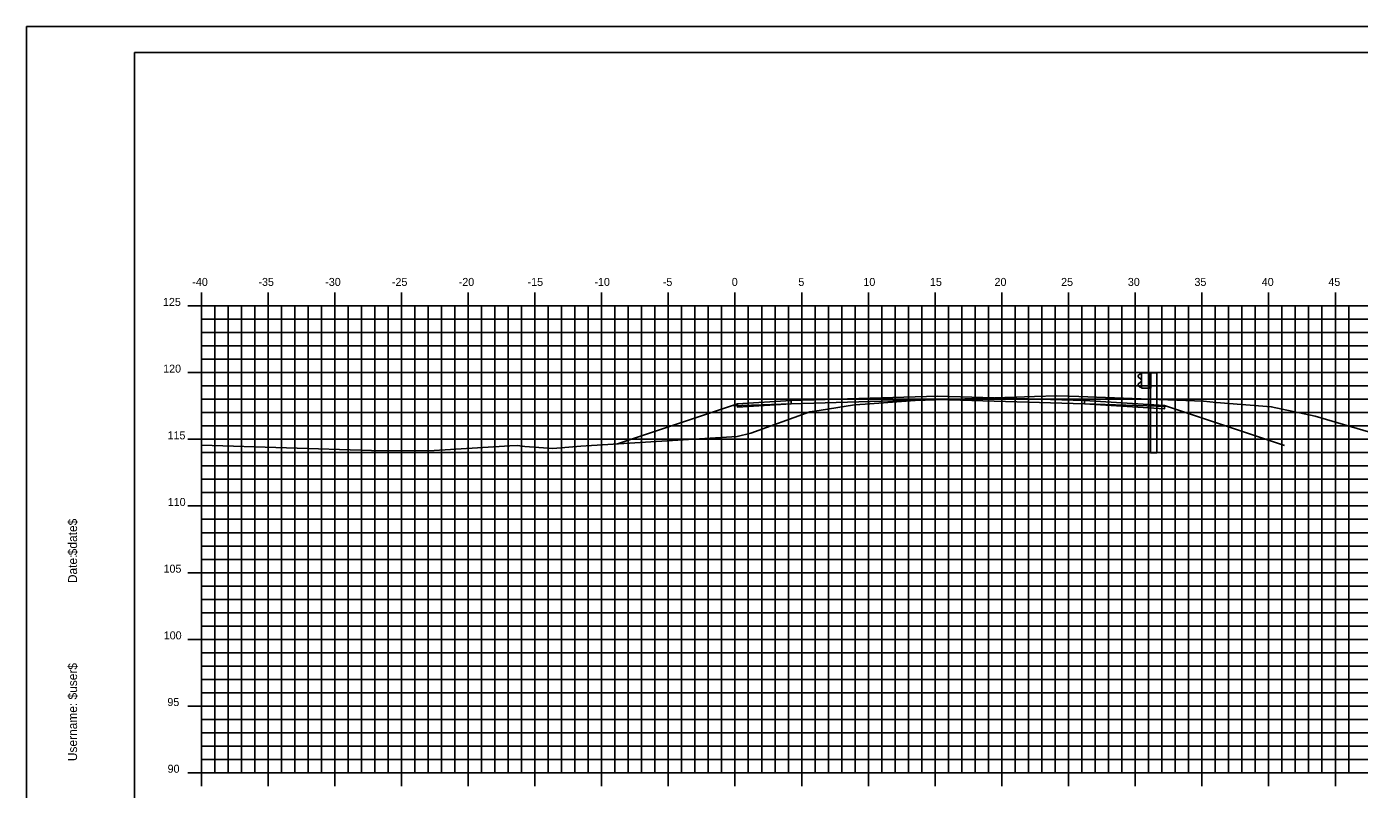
# Model space of a CAD drawing. Extents: x 850598 to 870284, y 366541 to 366651.
# Drawn here: x 851263.1 to 851363, y 366594 to 366651.2 of the extents above; entities that cross this region are included whole.
import ezdxf

# ---------------------------------------------------------------- set-up
doc = ezdxf.new("R2010")
doc.units = 0
for name, color, linetype in [('BORDER', 7, 'Continuous'), ('D_Guardrail_Beam_Rt', 7, 'Continuous'), ('D_Roadway_SubGrade', 7, 'Continuous'), ('H_V ANNOTATION', 7, 'Continuous'), ('MAJOR', 7, 'Continuous'), ('MINOR', 7, 'Continuous'), ('PLOT BOUNDARY', 7, 'Continuous'), ('S_Roadway_Centerline', 7, 'Continuous'), ('TEMPLATE', 7, 'Continuous')]:
    doc.layers.add(name, color=color, linetype=linetype)

msp = doc.modelspace()

# ---------------------------------------------------------------- linework, layer by layer
at = {"layer": 'BORDER'}
for p, q in [((851431.167, 366649.225), (851271.167, 366649.225)), ((851271.167, 366649.225), (851271.167, 366544.225))]:
    msp.add_line(p, q, dxfattribs=at)
at = {"layer": 'D_Guardrail_Beam_Rt'}
for p, q in [((851346.547, 366625.123), (851346.404, 366625.023)), ((851346.404, 366624.88), (851346.599, 366624.744)), ((851346.637, 366625.143), (851346.564, 366625.13)), ((851346.637, 366625.217), (851347.325, 366625.217)), ((851346.637, 366624.05), (851346.637, 366625.217)), ((851347.158, 366625.217), (851347.158, 366624.05)), ((851347.262, 366625.217), (851347.262, 366624.05)), ((851347.325, 366625.217), (851347.796, 366625.217)), ((851347.325, 366625.217), (851347.325, 366624.05)), ((851347.796, 366625.217), (851347.796, 366619.217)), ((851346.599, 366624.524), (851346.404, 366624.388)), ((851346.404, 366624.244), (851346.547, 366624.145)), ((851346.564, 366624.138), (851346.637, 366624.125)), ((851346.633, 366624.679), (851346.633, 366624.588)), ((851347.325, 366624.05), (851346.637, 366624.05)), ((851347.304, 366619.217), (851347.304, 366624.05)), ((851347.304, 366619.217), (851347.796, 366619.217))]:
    msp.add_line(p, q, dxfattribs=at)
for centre, major_axis, start_param, end_param in [((851346.454, 366624.951), (-0.0877, 0), 5.323254, 7.243116), ((851346.571, 366625.089), (-0.0417, 0), 4.886922, 5.323254), ((851346.454, 366624.316), (-0.0877, 0), 5.323254, 7.243116), ((851346.571, 366624.178), (-0.0417, 0), 0.959931, 1.396263), ((851346.554, 366624.679), (0.0789, 0), 0, 0.959931), ((851346.554, 366624.588), (0.0789, 0), 5.323254, 6.283185)]:
    msp.add_ellipse(centre, major_axis=major_axis, ratio=0.995501, start_param=start_param, end_param=end_param, dxfattribs=at)
at = {"layer": 'D_Roadway_SubGrade'}
msp.add_lwpolyline([(851357.367, 366619.764), (851348.367, 366622.764), (851342.367, 366623.124), (851331.367, 366623.454), (851320.367, 366623.124), (851316.367, 366622.884), (851307.367, 366619.884)], dxfattribs=at)
at = {"layer": 'MAJOR'}
for p, q in [((851276.167, 366631.227), (851276.167, 366630.225)), ((851276.167, 366631.227), (851276.167, 366630.225)), ((851281.167, 366631.227), (851281.167, 366630.225)), ((851281.167, 366631.227), (851281.167, 366630.225)), ((851286.167, 366631.227), (851286.167, 366630.225)), ((851286.167, 366631.227), (851286.167, 366630.225)), ((851291.167, 366631.227), (851291.167, 366630.225)), ((851291.167, 366631.227), (851291.167, 366630.225)), ((851296.167, 366631.227), (851296.167, 366630.225)), ((851296.167, 366631.227), (851296.167, 366630.225)), ((851301.167, 366631.227), (851301.167, 366630.225)), ((851301.167, 366631.227), (851301.167, 366630.225)), ((851306.167, 366631.227), (851306.167, 366630.225)), ((851306.167, 366631.227), (851306.167, 366630.225)), ((851311.167, 366631.227), (851311.167, 366630.225)), ((851311.167, 366631.227), (851311.167, 366630.225)), ((851316.167, 366631.227), (851316.167, 366630.225)), ((851316.167, 366631.227), (851316.167, 366630.225)), ((851321.167, 366631.227), (851321.167, 366630.225)), ((851321.167, 366631.227), (851321.167, 366630.225)), ((851326.167, 366631.227), (851326.167, 366630.225)), ((851326.167, 366631.227), (851326.167, 366630.225)), ((851331.167, 366631.227), (851331.167, 366630.225)), ((851331.167, 366631.227), (851331.167, 366630.225)), ((851336.167, 366631.227), (851336.167, 366630.225)), ((851336.167, 366631.227), (851336.167, 366630.225)), ((851341.167, 366631.227), (851341.167, 366630.225)), ((851341.167, 366631.227), (851341.167, 366630.225)), ((851346.167, 366631.227), (851346.167, 366630.225)), ((851346.167, 366631.227), (851346.167, 366630.225)), ((851351.167, 366631.227), (851351.167, 366630.225)), ((851351.167, 366631.227), (851351.167, 366630.225)), ((851356.167, 366631.227), (851356.167, 366630.225)), ((851356.167, 366631.227), (851356.167, 366630.225)), ((851361.167, 366631.227), (851361.167, 366630.225)), ((851361.167, 366631.227), (851361.167, 366630.225)), ((851275.165, 366630.225), (851276.167, 366630.225)), ((851275.165, 366630.225), (851276.167, 366630.225)), ((851276.167, 366630.225), (851416.167, 366630.225)), ((851276.167, 366595.225), (851276.167, 366630.225)), ((851276.167, 366595.225), (851276.167, 366630.225)), ((851276.167, 366630.225), (851416.167, 366630.225)), ((851276.167, 366630.225), (851416.167, 366630.225)), ((851276.167, 366595.225), (851276.167, 366630.225)), ((851276.167, 366595.225), (851276.167, 366630.225)), ((851276.167, 366630.225), (851416.167, 366630.225)), ((851281.167, 366595.225), (851281.167, 366630.225)), ((851281.167, 366595.225), (851281.167, 366630.225)), ((851286.167, 366595.225), (851286.167, 366630.225)), ((851286.167, 366595.225), (851286.167, 366630.225)), ((851291.167, 366595.225), (851291.167, 366630.225)), ((851291.167, 366595.225), (851291.167, 366630.225)), ((851296.167, 366595.225), (851296.167, 366630.225)), ((851296.167, 366595.225), (851296.167, 366630.225)), ((851301.167, 366595.225), (851301.167, 366630.225)), ((851301.167, 366595.225), (851301.167, 366630.225)), ((851306.167, 366595.225), (851306.167, 366630.225)), ((851306.167, 366595.225), (851306.167, 366630.225)), ((851311.167, 366595.225), (851311.167, 366630.225)), ((851311.167, 366595.225), (851311.167, 366630.225)), ((851316.167, 366595.225), (851316.167, 366630.225)), ((851316.167, 366595.225), (851316.167, 366630.225)), ((851321.167, 366595.225), (851321.167, 366630.225)), ((851321.167, 366595.225), (851321.167, 366630.225)), ((851326.167, 366595.225), (851326.167, 366630.225)), ((851326.167, 366595.225), (851326.167, 366630.225)), ((851331.167, 366595.225), (851331.167, 366630.225)), ((851331.167, 366595.225), (851331.167, 366630.225)), ((851336.167, 366595.225), (851336.167, 366630.225)), ((851336.167, 366595.225), (851336.167, 366630.225)), ((851341.167, 366595.225), (851341.167, 366630.225)), ((851341.167, 366595.225), (851341.167, 366630.225)), ((851346.167, 366595.225), (851346.167, 366630.225)), ((851346.167, 366595.225), (851346.167, 366630.225)), ((851351.167, 366595.225), (851351.167, 366630.225)), ((851351.167, 366595.225), (851351.167, 366630.225)), ((851356.167, 366595.225), (851356.167, 366630.225)), ((851356.167, 366595.225), (851356.167, 366630.225)), ((851361.167, 366595.225), (851361.167, 366630.225)), ((851361.167, 366595.225), (851361.167, 366630.225)), ((851275.165, 366625.225), (851276.167, 366625.225)), ((851275.165, 366625.225), (851276.167, 366625.225)), ((851276.167, 366625.225), (851416.167, 366625.225)), ((851276.167, 366625.225), (851416.167, 366625.225)), ((851275.165, 366620.225), (851276.167, 366620.225)), ((851275.165, 366620.225), (851276.167, 366620.225)), ((851276.167, 366620.225), (851416.167, 366620.225)), ((851276.167, 366620.225), (851416.167, 366620.225)), ((851275.165, 366615.225), (851276.167, 366615.225)), ((851275.165, 366615.225), (851276.167, 366615.225)), ((851276.167, 366615.225), (851416.167, 366615.225)), ((851276.167, 366615.225), (851416.167, 366615.225)), ((851275.165, 366610.225), (851276.167, 366610.225)), ((851275.165, 366610.225), (851276.167, 366610.225)), ((851276.167, 366610.225), (851416.167, 366610.225)), ((851276.167, 366610.225), (851416.167, 366610.225)), ((851275.165, 366605.225), (851276.167, 366605.225)), ((851275.165, 366605.225), (851276.167, 366605.225)), ((851276.167, 366605.225), (851416.167, 366605.225)), ((851276.167, 366605.225), (851416.167, 366605.225)), ((851275.165, 366600.225), (851276.167, 366600.225)), ((851275.165, 366600.225), (851276.167, 366600.225)), ((851276.167, 366600.225), (851416.167, 366600.225)), ((851276.167, 366600.225), (851416.167, 366600.225)), ((851275.165, 366595.225), (851276.167, 366595.225)), ((851275.165, 366595.225), (851276.167, 366595.225)), ((851276.167, 366595.225), (851416.167, 366595.225)), ((851276.167, 366595.225), (851416.167, 366595.225)), ((851276.167, 366594.223), (851276.167, 366595.225)), ((851276.167, 366595.225), (851416.167, 366595.225)), ((851276.167, 366595.225), (851416.167, 366595.225)), ((851276.167, 366594.223), (851276.167, 366595.225)), ((851281.167, 366594.223), (851281.167, 366595.225)), ((851281.167, 366594.223), (851281.167, 366595.225)), ((851286.167, 366594.223), (851286.167, 366595.225)), ((851286.167, 366594.223), (851286.167, 366595.225)), ((851291.167, 366594.223), (851291.167, 366595.225)), ((851291.167, 366594.223), (851291.167, 366595.225)), ((851296.167, 366594.223), (851296.167, 366595.225)), ((851296.167, 366594.223), (851296.167, 366595.225)), ((851301.167, 366594.223), (851301.167, 366595.225)), ((851301.167, 366594.223), (851301.167, 366595.225)), ((851306.167, 366594.223), (851306.167, 366595.225)), ((851306.167, 366594.223), (851306.167, 366595.225)), ((851311.167, 366594.223), (851311.167, 366595.225)), ((851311.167, 366594.223), (851311.167, 366595.225)), ((851316.167, 366594.223), (851316.167, 366595.225)), ((851316.167, 366594.223), (851316.167, 366595.225)), ((851321.167, 366594.223), (851321.167, 366595.225)), ((851321.167, 366594.223), (851321.167, 366595.225)), ((851326.167, 366594.223), (851326.167, 366595.225)), ((851326.167, 366594.223), (851326.167, 366595.225)), ((851331.167, 366594.223), (851331.167, 366595.225)), ((851331.167, 366594.223), (851331.167, 366595.225)), ((851336.167, 366594.223), (851336.167, 366595.225)), ((851336.167, 366594.223), (851336.167, 366595.225)), ((851341.167, 366594.223), (851341.167, 366595.225)), ((851341.167, 366594.223), (851341.167, 366595.225)), ((851346.167, 366594.223), (851346.167, 366595.225)), ((851346.167, 366594.223), (851346.167, 366595.225)), ((851351.167, 366594.223), (851351.167, 366595.225)), ((851351.167, 366594.223), (851351.167, 366595.225)), ((851356.167, 366594.223), (851356.167, 366595.225)), ((851356.167, 366594.223), (851356.167, 366595.225)), ((851361.167, 366594.223), (851361.167, 366595.225)), ((851361.167, 366594.223), (851361.167, 366595.225))]:
    msp.add_line(p, q, dxfattribs=at)
at = {"layer": 'MINOR'}
for p, q in [((851277.167, 366595.225), (851277.167, 366630.225)), ((851277.167, 366595.225), (851277.167, 366630.225)), ((851278.167, 366595.225), (851278.167, 366630.225)), ((851278.167, 366595.225), (851278.167, 366630.225)), ((851279.167, 366595.225), (851279.167, 366630.225)), ((851279.167, 366595.225), (851279.167, 366630.225)), ((851280.167, 366595.225), (851280.167, 366630.225)), ((851280.167, 366595.225), (851280.167, 366630.225)), ((851282.167, 366595.225), (851282.167, 366630.225)), ((851282.167, 366595.225), (851282.167, 366630.225)), ((851283.167, 366595.225), (851283.167, 366630.225)), ((851283.167, 366595.225), (851283.167, 366630.225)), ((851284.167, 366595.225), (851284.167, 366630.225)), ((851284.167, 366595.225), (851284.167, 366630.225)), ((851285.167, 366595.225), (851285.167, 366630.225)), ((851285.167, 366595.225), (851285.167, 366630.225)), ((851287.167, 366595.225), (851287.167, 366630.225)), ((851287.167, 366595.225), (851287.167, 366630.225)), ((851288.167, 366595.225), (851288.167, 366630.225)), ((851288.167, 366595.225), (851288.167, 366630.225)), ((851289.167, 366595.225), (851289.167, 366630.225)), ((851289.167, 366595.225), (851289.167, 366630.225)), ((851290.167, 366595.225), (851290.167, 366630.225)), ((851290.167, 366595.225), (851290.167, 366630.225)), ((851292.167, 366595.225), (851292.167, 366630.225)), ((851292.167, 366595.225), (851292.167, 366630.225)), ((851293.167, 366595.225), (851293.167, 366630.225)), ((851293.167, 366595.225), (851293.167, 366630.225)), ((851294.167, 366595.225), (851294.167, 366630.225)), ((851294.167, 366595.225), (851294.167, 366630.225)), ((851295.167, 366595.225), (851295.167, 366630.225)), ((851295.167, 366595.225), (851295.167, 366630.225)), ((851297.167, 366595.225), (851297.167, 366630.225)), ((851297.167, 366595.225), (851297.167, 366630.225)), ((851298.167, 366595.225), (851298.167, 366630.225)), ((851298.167, 366595.225), (851298.167, 366630.225)), ((851299.167, 366595.225), (851299.167, 366630.225)), ((851299.167, 366595.225), (851299.167, 366630.225)), ((851300.167, 366595.225), (851300.167, 366630.225)), ((851300.167, 366595.225), (851300.167, 366630.225)), ((851302.167, 366595.225), (851302.167, 366630.225)), ((851302.167, 366595.225), (851302.167, 366630.225)), ((851303.167, 366595.225), (851303.167, 366630.225)), ((851303.167, 366595.225), (851303.167, 366630.225)), ((851304.167, 366595.225), (851304.167, 366630.225)), ((851304.167, 366595.225), (851304.167, 366630.225)), ((851305.167, 366595.225), (851305.167, 366630.225)), ((851305.167, 366595.225), (851305.167, 366630.225)), ((851307.167, 366595.225), (851307.167, 366630.225)), ((851307.167, 366595.225), (851307.167, 366630.225)), ((851308.167, 366595.225), (851308.167, 366630.225)), ((851308.167, 366595.225), (851308.167, 366630.225)), ((851309.167, 366595.225), (851309.167, 366630.225)), ((851309.167, 366595.225), (851309.167, 366630.225)), ((851310.167, 366595.225), (851310.167, 366630.225)), ((851310.167, 366595.225), (851310.167, 366630.225)), ((851312.167, 366595.225), (851312.167, 366630.225)), ((851312.167, 366595.225), (851312.167, 366630.225)), ((851313.167, 366595.225), (851313.167, 366630.225)), ((851313.167, 366595.225), (851313.167, 366630.225)), ((851314.167, 366595.225), (851314.167, 366630.225)), ((851314.167, 366595.225), (851314.167, 366630.225)), ((851315.167, 366595.225), (851315.167, 366630.225)), ((851315.167, 366595.225), (851315.167, 366630.225)), ((851317.167, 366595.225), (851317.167, 366630.225)), ((851317.167, 366595.225), (851317.167, 366630.225)), ((851318.167, 366595.225), (851318.167, 366630.225)), ((851318.167, 366595.225), (851318.167, 366630.225)), ((851319.167, 366595.225), (851319.167, 366630.225)), ((851319.167, 366595.225), (851319.167, 366630.225)), ((851320.167, 366595.225), (851320.167, 366630.225)), ((851320.167, 366595.225), (851320.167, 366630.225)), ((851322.167, 366595.225), (851322.167, 366630.225)), ((851322.167, 366595.225), (851322.167, 366630.225)), ((851323.167, 366595.225), (851323.167, 366630.225)), ((851323.167, 366595.225), (851323.167, 366630.225)), ((851324.167, 366595.225), (851324.167, 366630.225)), ((851324.167, 366595.225), (851324.167, 366630.225)), ((851325.167, 366595.225), (851325.167, 366630.225)), ((851325.167, 366595.225), (851325.167, 366630.225)), ((851327.167, 366595.225), (851327.167, 366630.225)), ((851327.167, 366595.225), (851327.167, 366630.225)), ((851328.167, 366595.225), (851328.167, 366630.225)), ((851328.167, 366595.225), (851328.167, 366630.225)), ((851329.167, 366595.225), (851329.167, 366630.225)), ((851329.167, 366595.225), (851329.167, 366630.225)), ((851330.167, 366595.225), (851330.167, 366630.225)), ((851330.167, 366595.225), (851330.167, 366630.225)), ((851332.167, 366595.225), (851332.167, 366630.225)), ((851332.167, 366595.225), (851332.167, 366630.225)), ((851333.167, 366595.225), (851333.167, 366630.225)), ((851333.167, 366595.225), (851333.167, 366630.225)), ((851334.167, 366595.225), (851334.167, 366630.225)), ((851334.167, 366595.225), (851334.167, 366630.225)), ((851335.167, 366595.225), (851335.167, 366630.225)), ((851335.167, 366595.225), (851335.167, 366630.225)), ((851337.167, 366595.225), (851337.167, 366630.225)), ((851337.167, 366595.225), (851337.167, 366630.225)), ((851338.167, 366595.225), (851338.167, 366630.225)), ((851338.167, 366595.225), (851338.167, 366630.225)), ((851339.167, 366595.225), (851339.167, 366630.225)), ((851339.167, 366595.225), (851339.167, 366630.225)), ((851340.167, 366595.225), (851340.167, 366630.225)), ((851340.167, 366595.225), (851340.167, 366630.225)), ((851342.167, 366595.225), (851342.167, 366630.225)), ((851342.167, 366595.225), (851342.167, 366630.225)), ((851343.167, 366595.225), (851343.167, 366630.225)), ((851343.167, 366595.225), (851343.167, 366630.225)), ((851344.167, 366595.225), (851344.167, 366630.225)), ((851344.167, 366595.225), (851344.167, 366630.225)), ((851345.167, 366595.225), (851345.167, 366630.225)), ((851345.167, 366595.225), (851345.167, 366630.225)), ((851347.167, 366595.225), (851347.167, 366630.225)), ((851347.167, 366595.225), (851347.167, 366630.225)), ((851348.167, 366595.225), (851348.167, 366630.225)), ((851348.167, 366595.225), (851348.167, 366630.225)), ((851349.167, 366595.225), (851349.167, 366630.225)), ((851349.167, 366595.225), (851349.167, 366630.225)), ((851350.167, 366595.225), (851350.167, 366630.225)), ((851350.167, 366595.225), (851350.167, 366630.225)), ((851352.167, 366595.225), (851352.167, 366630.225)), ((851352.167, 366595.225), (851352.167, 366630.225)), ((851353.167, 366595.225), (851353.167, 366630.225)), ((851353.167, 366595.225), (851353.167, 366630.225)), ((851354.167, 366595.225), (851354.167, 366630.225)), ((851354.167, 366595.225), (851354.167, 366630.225)), ((851355.167, 366595.225), (851355.167, 366630.225)), ((851355.167, 366595.225), (851355.167, 366630.225)), ((851357.167, 366595.225), (851357.167, 366630.225)), ((851357.167, 366595.225), (851357.167, 366630.225)), ((851358.167, 366595.225), (851358.167, 366630.225)), ((851358.167, 366595.225), (851358.167, 366630.225)), ((851359.167, 366595.225), (851359.167, 366630.225)), ((851359.167, 366595.225), (851359.167, 366630.225)), ((851360.167, 366595.225), (851360.167, 366630.225)), ((851360.167, 366595.225), (851360.167, 366630.225)), ((851362.167, 366595.225), (851362.167, 366630.225)), ((851362.167, 366595.225), (851362.167, 366630.225)), ((851276.167, 366629.225), (851416.167, 366629.225)), ((851276.167, 366629.225), (851277.169, 366629.225)), ((851276.167, 366629.225), (851416.167, 366629.225)), ((851276.167, 366629.225), (851277.169, 366629.225)), ((851276.167, 366628.225), (851416.167, 366628.225)), ((851276.167, 366628.225), (851277.169, 366628.225)), ((851276.167, 366628.225), (851416.167, 366628.225)), ((851276.167, 366628.225), (851277.169, 366628.225)), ((851276.167, 366627.225), (851416.167, 366627.225)), ((851276.167, 366627.225), (851277.169, 366627.225)), ((851276.167, 366627.225), (851416.167, 366627.225)), ((851276.167, 366627.225), (851277.169, 366627.225)), ((851276.167, 366626.225), (851416.167, 366626.225)), ((851276.167, 366626.225), (851277.169, 366626.225)), ((851276.167, 366626.225), (851416.167, 366626.225)), ((851276.167, 366626.225), (851277.169, 366626.225)), ((851276.167, 366624.225), (851416.167, 366624.225)), ((851276.167, 366624.225), (851277.169, 366624.225)), ((851276.167, 366624.225), (851416.167, 366624.225)), ((851276.167, 366624.225), (851277.169, 366624.225)), ((851276.167, 366623.225), (851416.167, 366623.225)), ((851276.167, 366623.225), (851277.169, 366623.225)), ((851276.167, 366623.225), (851416.167, 366623.225)), ((851276.167, 366623.225), (851277.169, 366623.225)), ((851276.167, 366622.225), (851416.167, 366622.225)), ((851276.167, 366622.225), (851277.169, 366622.225)), ((851276.167, 366622.225), (851416.167, 366622.225)), ((851276.167, 366622.225), (851277.169, 366622.225)), ((851276.167, 366621.225), (851416.167, 366621.225)), ((851276.167, 366621.225), (851277.169, 366621.225)), ((851276.167, 366621.225), (851416.167, 366621.225)), ((851276.167, 366621.225), (851277.169, 366621.225)), ((851276.167, 366619.225), (851416.167, 366619.225)), ((851276.167, 366619.225), (851277.169, 366619.225)), ((851276.167, 366619.225), (851416.167, 366619.225)), ((851276.167, 366619.225), (851277.169, 366619.225)), ((851276.167, 366618.225), (851416.167, 366618.225)), ((851276.167, 366618.225), (851277.169, 366618.225)), ((851276.167, 366618.225), (851416.167, 366618.225)), ((851276.167, 366618.225), (851277.169, 366618.225)), ((851276.167, 366617.225), (851416.167, 366617.225)), ((851276.167, 366617.225), (851277.169, 366617.225)), ((851276.167, 366617.225), (851416.167, 366617.225)), ((851276.167, 366617.225), (851277.169, 366617.225)), ((851276.167, 366616.225), (851416.167, 366616.225)), ((851276.167, 366616.225), (851277.169, 366616.225)), ((851276.167, 366616.225), (851416.167, 366616.225)), ((851276.167, 366616.225), (851277.169, 366616.225)), ((851276.167, 366614.225), (851416.167, 366614.225)), ((851276.167, 366614.225), (851277.169, 366614.225)), ((851276.167, 366614.225), (851416.167, 366614.225)), ((851276.167, 366614.225), (851277.169, 366614.225)), ((851276.167, 366613.225), (851416.167, 366613.225)), ((851276.167, 366613.225), (851277.169, 366613.225)), ((851276.167, 366613.225), (851416.167, 366613.225)), ((851276.167, 366613.225), (851277.169, 366613.225)), ((851276.167, 366612.225), (851416.167, 366612.225)), ((851276.167, 366612.225), (851277.169, 366612.225)), ((851276.167, 366612.225), (851416.167, 366612.225)), ((851276.167, 366612.225), (851277.169, 366612.225)), ((851276.167, 366611.225), (851416.167, 366611.225)), ((851276.167, 366611.225), (851277.169, 366611.225)), ((851276.167, 366611.225), (851416.167, 366611.225)), ((851276.167, 366611.225), (851277.169, 366611.225)), ((851276.167, 366609.225), (851416.167, 366609.225)), ((851276.167, 366609.225), (851277.169, 366609.225)), ((851276.167, 366609.225), (851416.167, 366609.225)), ((851276.167, 366609.225), (851277.169, 366609.225)), ((851276.167, 366608.225), (851416.167, 366608.225)), ((851276.167, 366608.225), (851277.169, 366608.225)), ((851276.167, 366608.225), (851416.167, 366608.225)), ((851276.167, 366608.225), (851277.169, 366608.225)), ((851276.167, 366607.225), (851416.167, 366607.225)), ((851276.167, 366607.225), (851277.169, 366607.225)), ((851276.167, 366607.225), (851416.167, 366607.225)), ((851276.167, 366607.225), (851277.169, 366607.225)), ((851276.167, 366606.225), (851416.167, 366606.225)), ((851276.167, 366606.225), (851277.169, 366606.225)), ((851276.167, 366606.225), (851416.167, 366606.225)), ((851276.167, 366606.225), (851277.169, 366606.225)), ((851276.167, 366604.225), (851416.167, 366604.225)), ((851276.167, 366604.225), (851277.169, 366604.225)), ((851276.167, 366604.225), (851416.167, 366604.225)), ((851276.167, 366604.225), (851277.169, 366604.225)), ((851276.167, 366603.225), (851416.167, 366603.225)), ((851276.167, 366603.225), (851277.169, 366603.225)), ((851276.167, 366603.225), (851416.167, 366603.225)), ((851276.167, 366603.225), (851277.169, 366603.225)), ((851276.167, 366602.225), (851416.167, 366602.225)), ((851276.167, 366602.225), (851277.169, 366602.225)), ((851276.167, 366602.225), (851416.167, 366602.225)), ((851276.167, 366602.225), (851277.169, 366602.225)), ((851276.167, 366601.225), (851416.167, 366601.225)), ((851276.167, 366601.225), (851277.169, 366601.225)), ((851276.167, 366601.225), (851416.167, 366601.225)), ((851276.167, 366601.225), (851277.169, 366601.225)), ((851276.167, 366599.225), (851416.167, 366599.225)), ((851276.167, 366599.225), (851277.169, 366599.225)), ((851276.167, 366599.225), (851416.167, 366599.225)), ((851276.167, 366599.225), (851277.169, 366599.225)), ((851276.167, 366598.225), (851416.167, 366598.225)), ((851276.167, 366598.225), (851277.169, 366598.225)), ((851276.167, 366598.225), (851416.167, 366598.225)), ((851276.167, 366598.225), (851277.169, 366598.225)), ((851276.167, 366597.225), (851416.167, 366597.225)), ((851276.167, 366597.225), (851277.169, 366597.225)), ((851276.167, 366597.225), (851416.167, 366597.225)), ((851276.167, 366597.225), (851277.169, 366597.225)), ((851276.167, 366596.225), (851416.167, 366596.225)), ((851276.167, 366596.225), (851277.169, 366596.225)), ((851276.167, 366596.225), (851416.167, 366596.225)), ((851276.167, 366596.225), (851277.169, 366596.225))]:
    msp.add_line(p, q, dxfattribs=at)
at = {"layer": 'PLOT BOUNDARY'}
msp.add_lwpolyline([(851263.073, 366541.166), (851433.073, 366541.166), (851433.073, 366651.166), (851263.073, 366651.166)], close=True, dxfattribs=at)
at = {"layer": 'S_Roadway_Centerline'}
msp.add_lwpolyline([(851276.167, 366619.783), (851288.918, 366619.377), (851293.213, 366619.352), (851299.296, 366619.735), (851299.864, 366619.749), (851300.419, 366619.676), (851302.505, 366619.546), (851304.609, 366619.72), (851316.335, 366620.443), (851317.364, 366620.686), (851321.789, 366622.277), (851322.481, 366622.386), (851325.122, 366622.817), (851325.937, 366622.867), (851329.661, 366623.127), (851338.606, 366623.44), (851340.295, 366623.497), (851341.935, 366623.445), (851351.282, 366623.087), (851352.246, 366622.985), (851356.369, 366622.671), (851359.661, 366621.961), (851368.488, 366619.362)], dxfattribs=at)
at = {"layer": 'TEMPLATE'}
for points in [[(851315.938, 366622.741), (851320.367, 366622.874), (851331.367, 366623.204), (851342.367, 366622.874), (851348.597, 366622.687)], [(851316.367, 366622.884), (851316.367, 366622.634), (851320.367, 366622.874)], [(851320.367, 366623.124), (851320.367, 366622.874), (851331.367, 366623.204), (851342.367, 366622.874), (851342.367, 366623.124)], [(851342.367, 366622.874), (851348.367, 366622.514), (851348.367, 366622.764)]]:
    msp.add_lwpolyline(points, dxfattribs=at)

# ---------------------------------------------------------------- texts
at = {"layer": 'BORDER'}
for s, p in [('$date$', (851266.852, 366611.53)), ('Date:', (851266.852, 366609.442)), ('$user$', (851266.852, 366600.717)), ('Username:', (851266.852, 366596.093))]:
    msp.add_text(s, height=0.6696, rotation=90, dxfattribs=at).set_placement(p)
at = {"layer": 'H_V ANNOTATION'}
for s, p in [('-40', (851275.492, 366631.725)), ('-35', (851280.447, 366631.725)), ('-30', (851285.455, 366631.725)), ('-25', (851290.452, 366631.725)), ('-20', (851295.46, 366631.725)), ('-15', (851300.623, 366631.725)), ('-10', (851305.631, 366631.725)), ('-5', (851310.757, 366631.725)), ('0', (851315.926, 366631.725)), ('5', (851320.918, 366631.725)), ('10', (851325.792, 366631.725)), ('15', (851330.784, 366631.725)), ('20', (851335.621, 366631.725)), ('25', (851340.613, 366631.725)), ('30', (851345.615, 366631.725)), ('35', (851350.607, 366631.725)), ('40', (851355.653, 366631.725)), ('45', (851360.645, 366631.725)), ('125', (851273.291, 366630.225)), ('120', (851273.307, 366625.225)), ('115', (851273.634, 366620.225)), ('110', (851273.65, 366615.225)), ('105', (851273.334, 366610.225)), ('100', (851273.35, 366605.225)), ('95', (851273.623, 366600.225)), ('90', (851273.639, 366595.225))]:
    msp.add_text(s, height=0.6, dxfattribs=at).set_placement(p)

doc.saveas('drawing.dxf')
